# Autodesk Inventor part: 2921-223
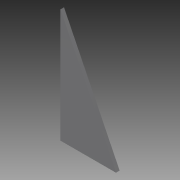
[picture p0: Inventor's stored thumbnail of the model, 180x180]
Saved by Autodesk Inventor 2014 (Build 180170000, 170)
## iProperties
Company: NHTSA/VRTC
Created: 2012-08
Part Number: 2921-223
Material: Steel, Mild
Document SubType Name: Modeling
Designer: Mike Vanvoorhis
Density: 7.86 g/cm^3
Mass: 1631.66 g
Surface Area: 509.874 cm^2
Volume: 207.591 cm^3
Project: CHILD SIDE IMPACT SLED
Description: IMPACTOR STOP CENTER GUSSET PLATE
Stock Number: PL 9.5 (3/8") x 146.1 (5 3/4") x 298.5 (11 3/4")
Appearance: Steel
Author: Dave Walker
Title: Impactor Stop Gusset Plate
Subject: Child Side Impact Sled
Revision Number: A
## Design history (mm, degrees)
sketch "Sketch1"
  geometry: L1 (0, 0)-(146.05, 0); L2 (0, 0)-(0, 298.45); L3 (0, 298.45)-(146.05, 0)
  constraints: 6 end point, 1 horizontal, 1 perpendicular
  dimensions: "d0" = 146.05 distance of L1.start L1.end; "d1" = 298.45 distance of L1.start L2.end
extrude "Extrusion1" new body sketch "Sketch1" distance "d2" = 9.525; taper "d3" = 0 deg
body "Solid1"
